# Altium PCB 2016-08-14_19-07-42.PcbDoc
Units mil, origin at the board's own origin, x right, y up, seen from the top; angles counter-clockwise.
Board outline 2760 x 2755 mil, 4 copper layers (Top Layer, MidLayer1, MidLayer2, Bottom Layer); 18 components, 10 nets, 39 pads, 47 vias.
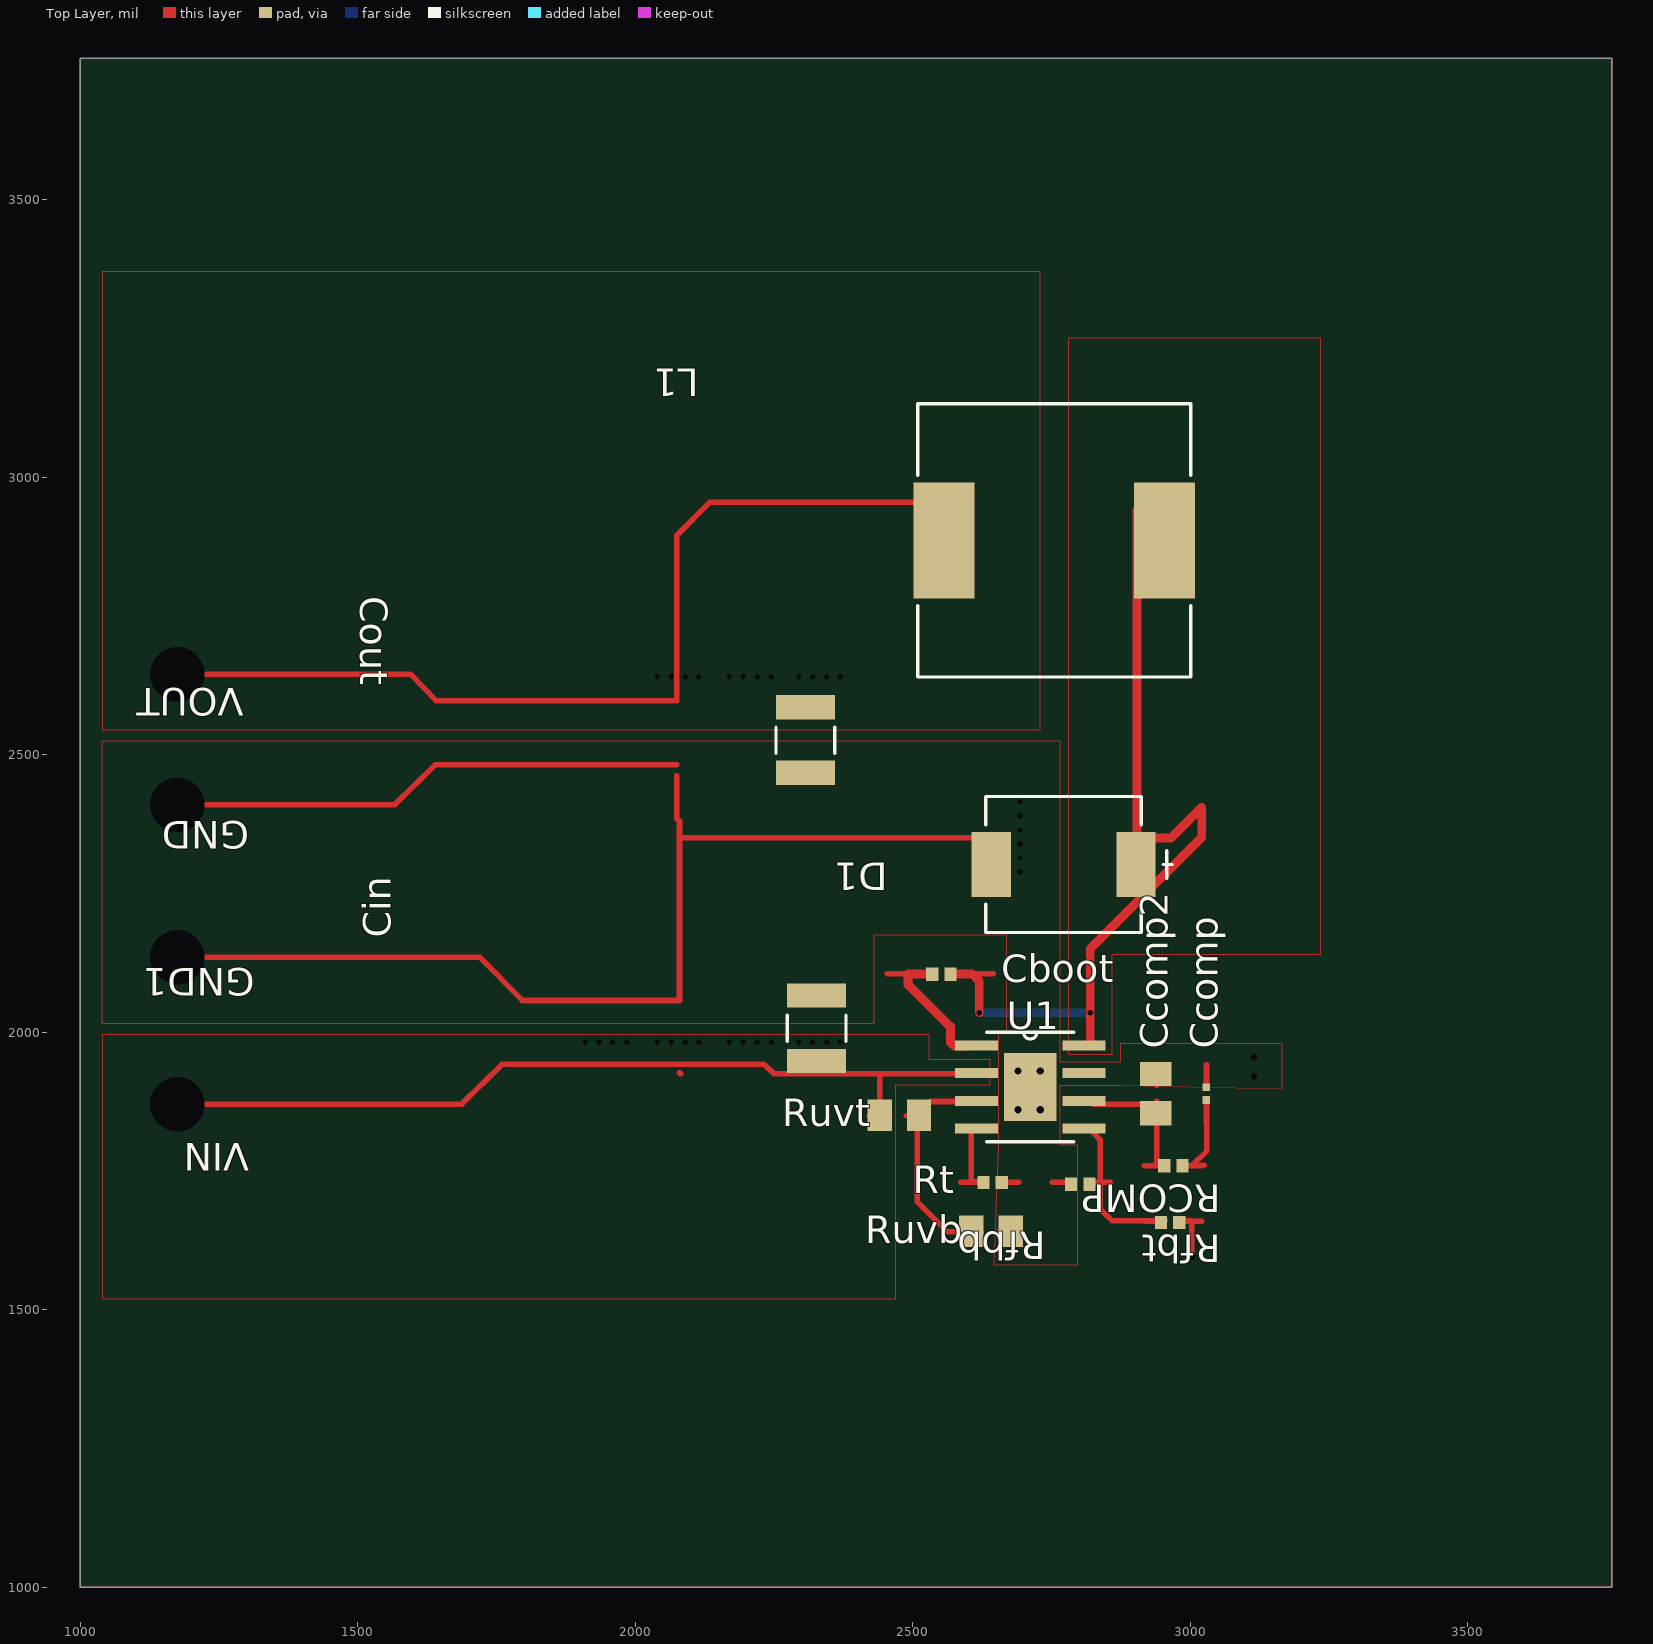
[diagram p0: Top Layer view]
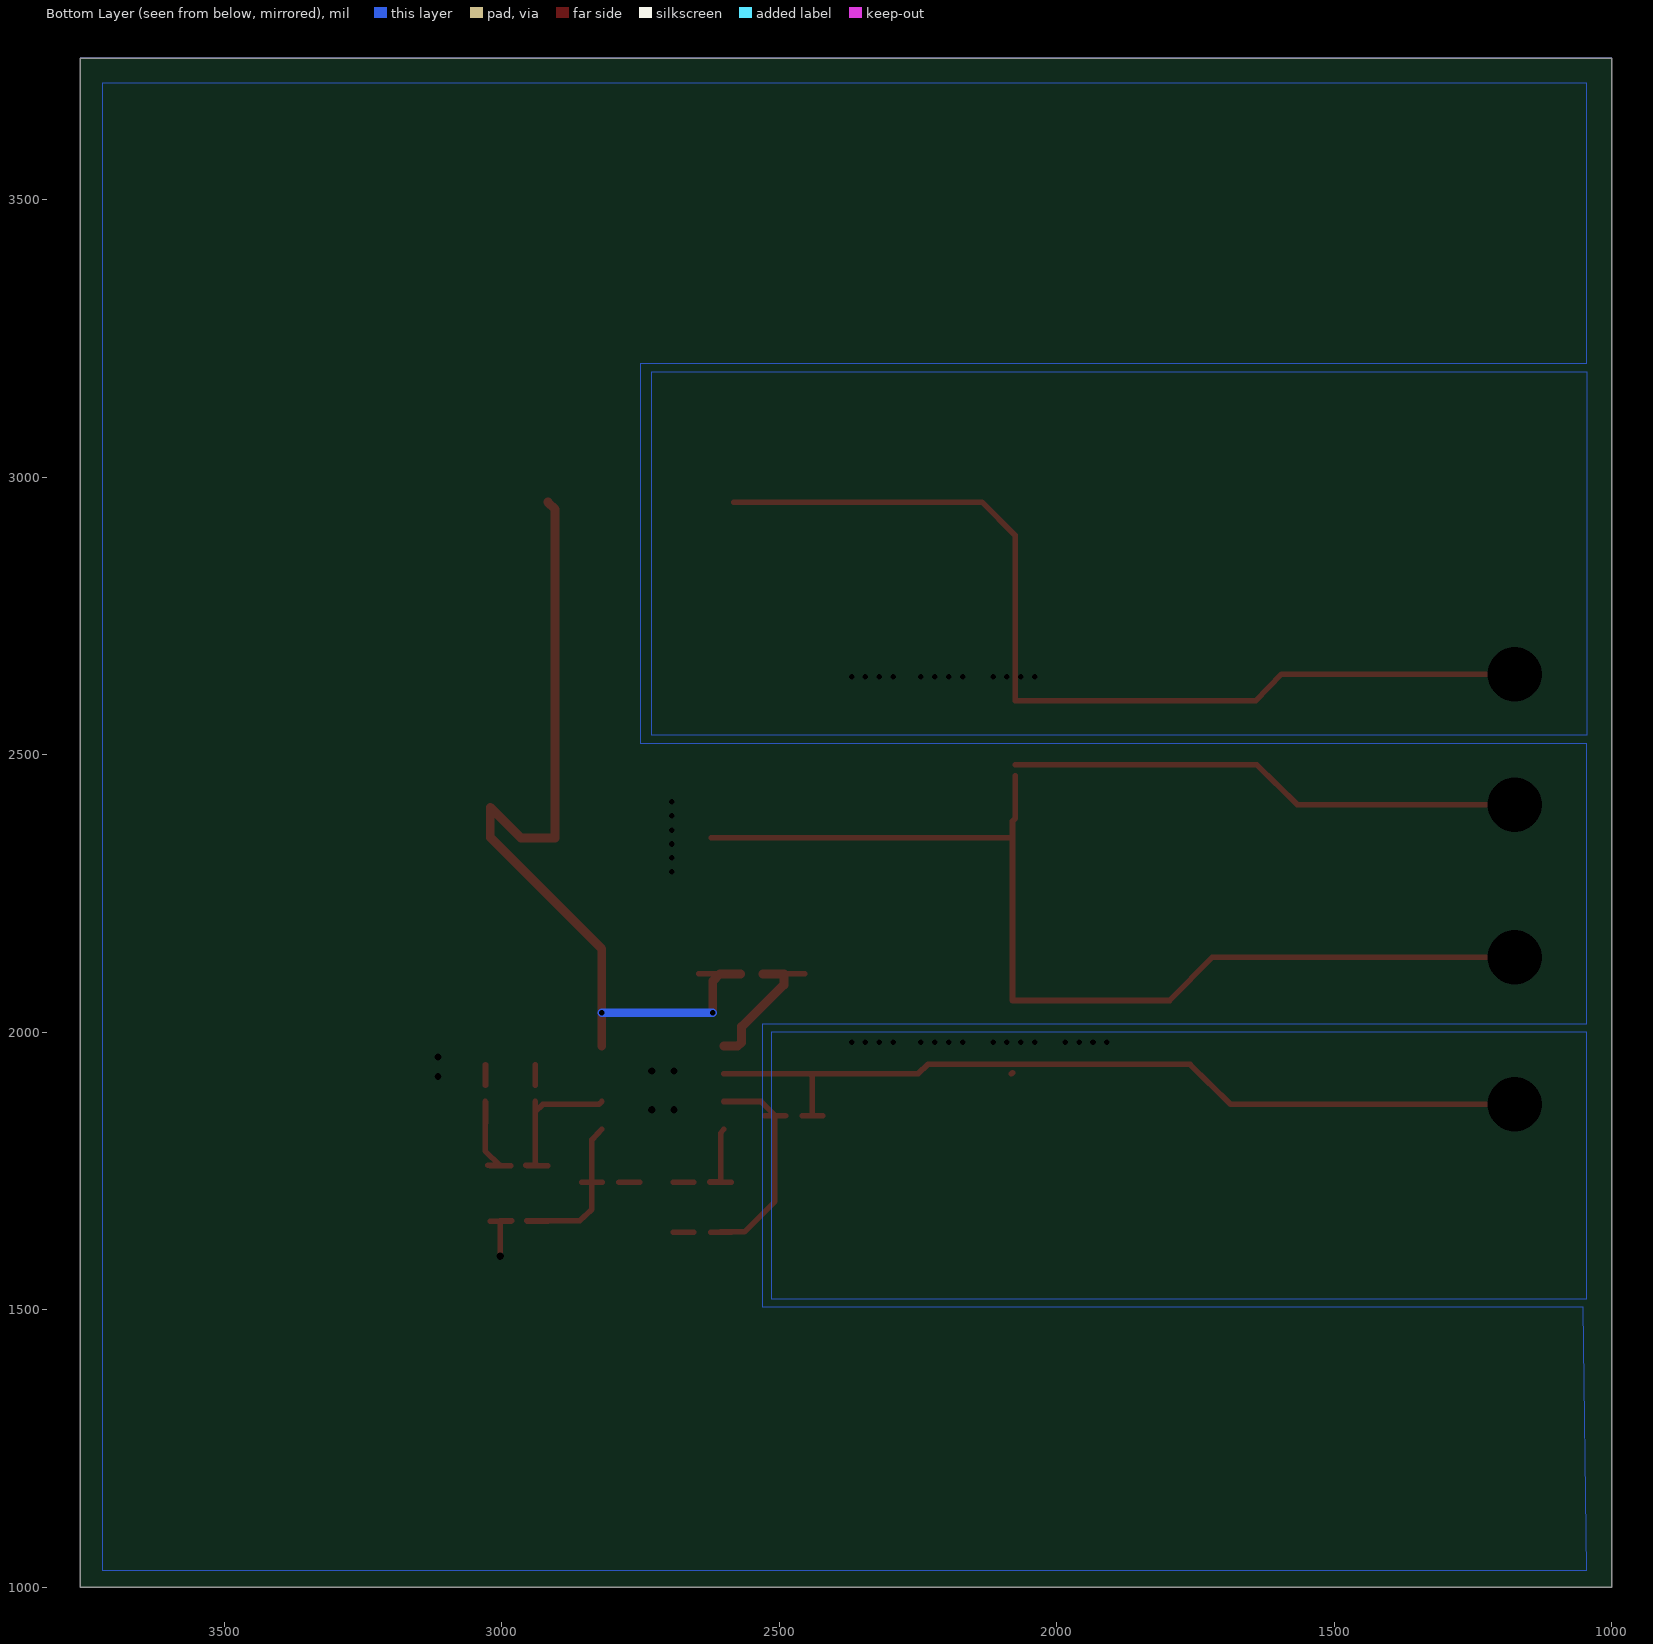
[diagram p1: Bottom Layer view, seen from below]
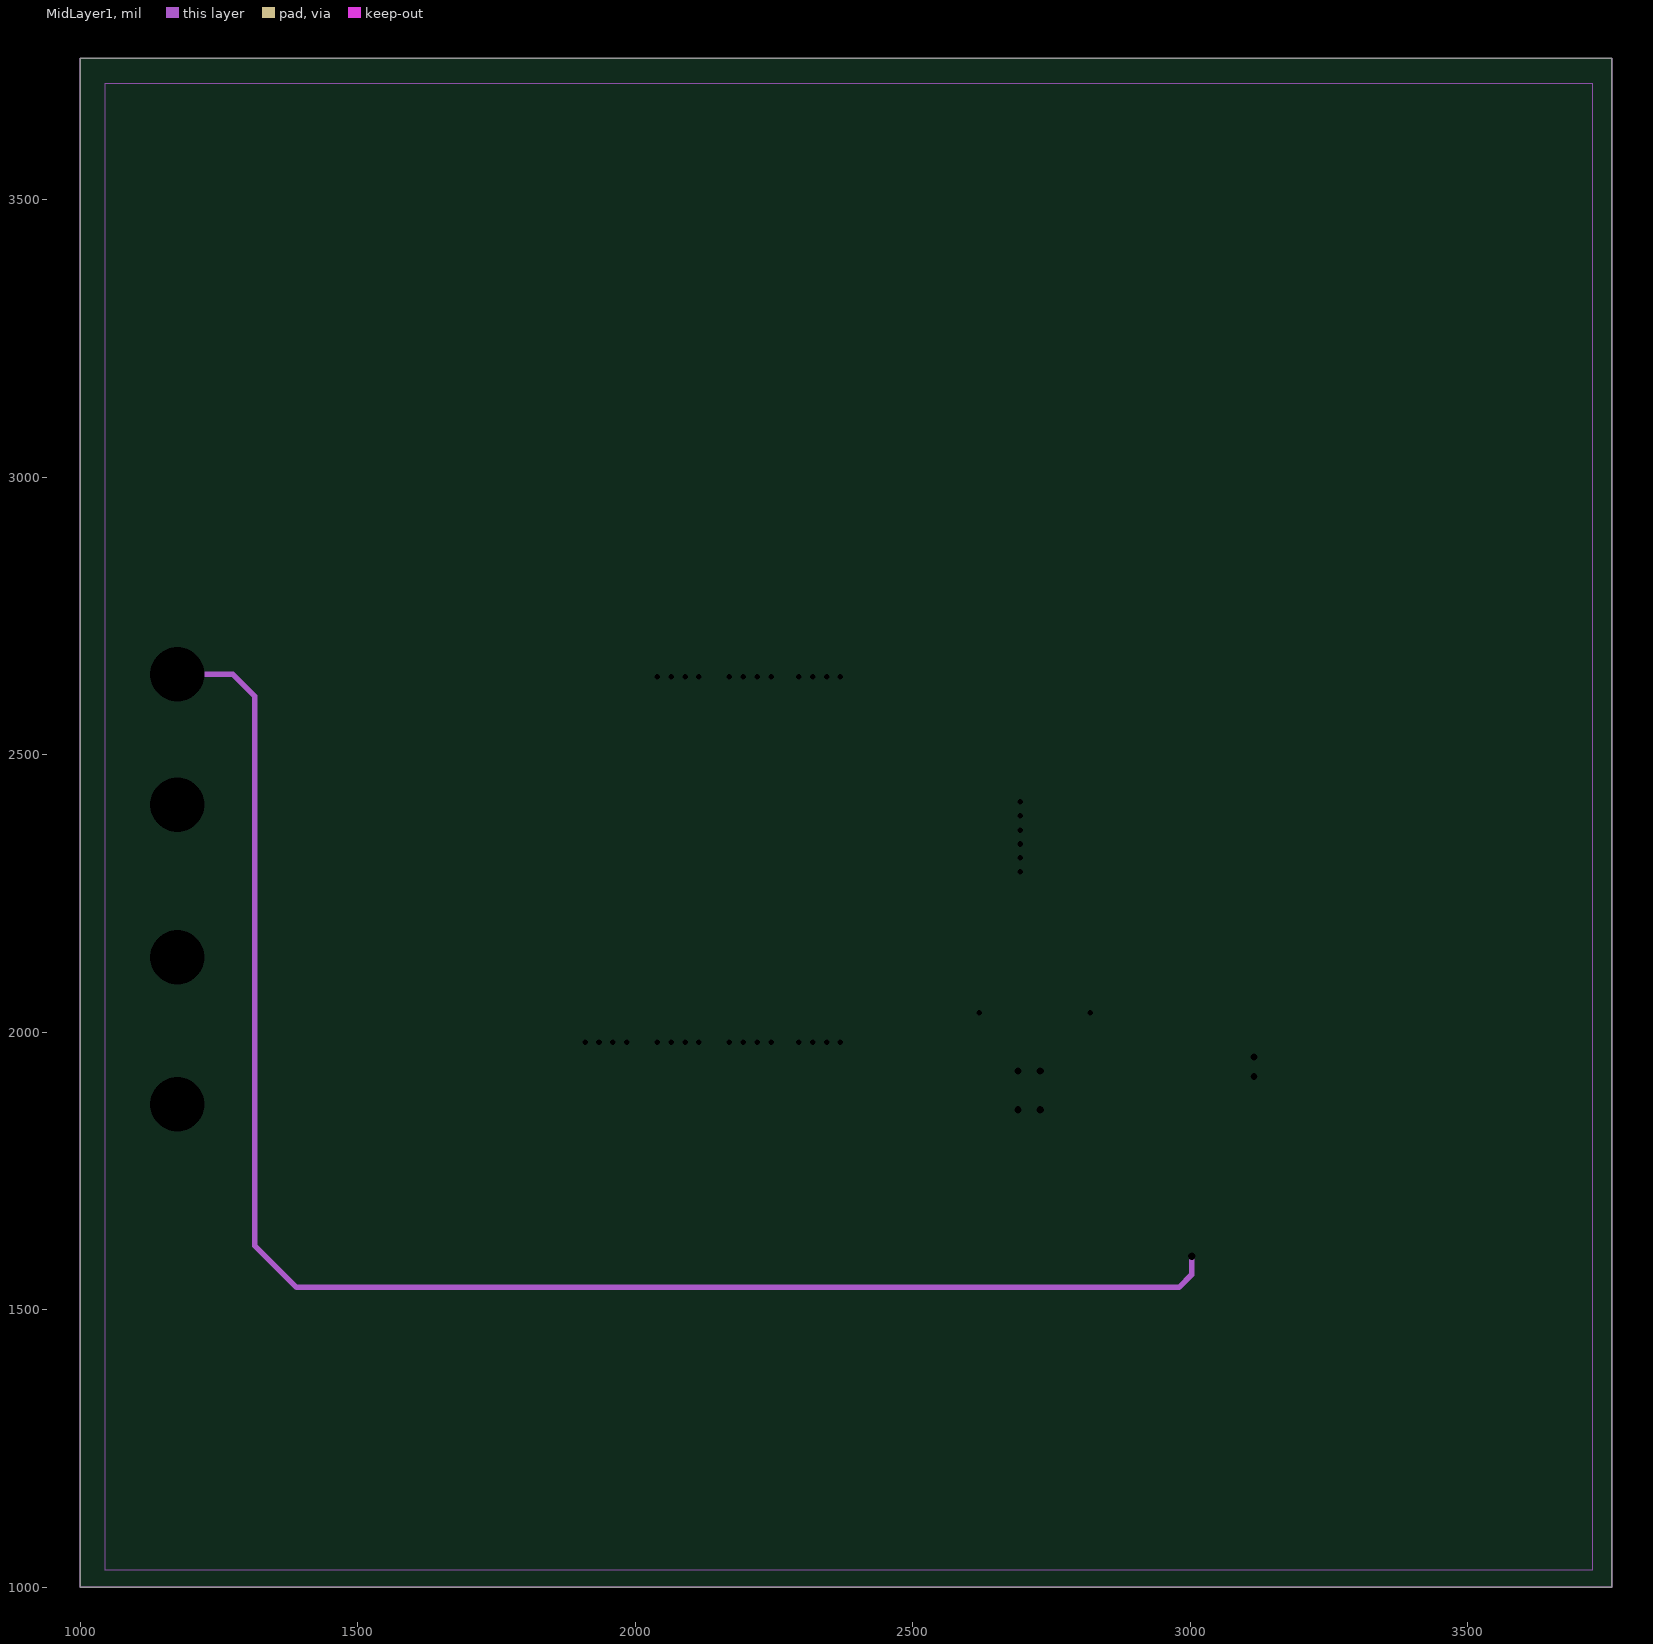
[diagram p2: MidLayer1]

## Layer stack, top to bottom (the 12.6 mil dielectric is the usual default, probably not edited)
Top Layer: signal copper 1.4
Dielectric: core 12.6, FR-4, Dk 4.8
MidLayer1: signal copper 1.4
Dielectric: prepreg 12.6, FR-4, Dk 4.8
MidLayer2: signal copper 1.4
Dielectric: core 12.6, FR-4, Dk 4.8
Bottom Layer: signal copper 1.4

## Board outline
1000,1000 3760,1000 3760,3755 1000,3755

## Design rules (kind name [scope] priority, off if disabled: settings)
PlaneConnect [All] p0: scope1count=1 scope1_0_kind=Board scope1_0_value=Board scope2count=1 scope2_0_kind=Board scope2_0_value=Board commentlength=0 planeconnectstyle=Direct reliefexpansion=20 reliefentries=4 reliefconductorwidth=10 reliefairgap=10
PlaneConnect [All] p1: planeconnectstyle=Direct reliefexpansion=20 reliefentries=4 reliefconductorwidth=10 reliefairgap=10
PolygonConnect [All] p0: scope1count=1 scope1_0_kind=Board scope1_0_value=Board scope2count=1 scope2_0_kind=Board scope2_0_value=Board commentlength=0 connectstyle=Direct reliefconductorwidth=10 reliefentries=4 polygonreliefangle="90 Angle"
PolygonConnect [All] p1: connectstyle=Direct reliefconductorwidth=10 reliefentries=4 polygonreliefangle="90 Angle"

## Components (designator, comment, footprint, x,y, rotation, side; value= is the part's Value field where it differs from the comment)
Cboot "" 0402 2552,2104 r0 top
Ccomp "" 0201 3029,1889 r90 top
Ccomp2 "" 0805 2938,1889 r90 top
Cin "" 1210 2327,2007 r90 top
Cout "" 1210_280 2307,2526 r270 top
D1 "" SMC 2772,2302 r180 top
GND "" TP-1502 1174,2409 r180 top
GND1 "" TP-1502 1174,2133 r180 top
L1 "" SRR1210 2755,2886 r180 top
RCOMP "" 0402 2970,1759 r180 top
Rfbb "" 0402 2802,1726 r180 top
Rfbt "" 0402 2964,1657 r180 top
Rt "" 0402 2644,1729 r0 top
Ruvb "" 0805 2641,1641 r0 top
Ruvt "" 0805 2476,1850 r0 top
U1 "" R-PDSO-G8 2712,1901 r0 top
VIN "" TP-1502 1174,1870 r180 top
VOUT "" TP-1502 1174,2644 r180 top

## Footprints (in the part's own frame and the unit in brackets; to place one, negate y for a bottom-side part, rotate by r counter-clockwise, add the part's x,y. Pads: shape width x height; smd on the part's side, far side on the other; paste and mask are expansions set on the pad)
0201 [mil]
  rect 14x13 smd: 1(-11.5,0) 2(11.5,0)
0402 [mil]
  rect 22x24 smd: 1(-16.5,0) 2(16.5,0)
0805 [mil]
  rect 44x57 smd: 1(-35.5,0) 2(35.5,0)
1210 [mil]
  rect 44x106 smd: 1(-59,0) 2(59,0)
  silkscreen extent -24,-53 24,53
1210_280 [mil]
  rect 44x106 smd: 1(-59,0) 2(59,0)
  silkscreen extent -24,-53 24,53
R-PDSO-G8 [mil]
  rect 78x18.14 smd: 1(-97,75) 2(-97,25) 3(-97,-25) 4(-97,-75) 5(97,-75) 6(97,-25) 7(97,25) 8(97,75)
  rect 94x122 smd: 9(0,0)
  silkscreen extent -78,-98 78,98
SMC [mil]
  rect 71x117 smd: 1(-130.5,0) 2(130.5,0)
  silkscreen extent -196,-123 140,123
SRR1210 [mil]
  rect 110x209 smd: 1(-198.5,0) 2(198.5,0)
  silkscreen extent -246,-246 246,246
TP-1502 [mil]
  round 65 / inner round 0 / far side round 65 hole 32: 1(0,0)

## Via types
v1: diameter 0, hole 10, Top Layer to Bottom Layer, 36 vias
v2: diameter 0, hole 13, Top Layer to Bottom Layer, 7 vias
v3: diameter 0, hole 98, Top Layer to Bottom Layer, 4 vias

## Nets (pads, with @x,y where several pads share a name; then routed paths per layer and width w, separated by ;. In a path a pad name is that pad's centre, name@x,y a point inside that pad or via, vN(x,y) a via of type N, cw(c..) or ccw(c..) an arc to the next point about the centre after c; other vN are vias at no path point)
0: Ccomp2.2 Ccomp.2 Cin.2 Cout.2 D1.2 GND1.1 GND.1 Rfbb.2 Rt.2 Ruvb.2 U1.7 U1.9 | length 3002.2
  Top Layer w10: v3(1175,2135) 1720,2135 1797,2057 2080,2057 2080,2350 ; v3(1175,2410) 1567,2410 1640,2482 2075,2482 ; 2075,2462 2075,2385 2080,2380 2080,2350 ; D1.2@2623,2350 2080,2350 ; 2654,1639.5 Ruvb.2@2691,1639.5 ; Rt.2@2654,1729.5 2691,1729.5 ; 2752,1729.5 Rfbb.2@2789,1729.5 ; Ccomp2.2@2939.5,1904 Ccomp2.2@2939.5,1941 ; Ccomp.2@3029.5,1904 3029.5,1941
  other v1: 2694,2289 2694,2314 2694,2339 2694,2364 2694,2390 2694,2415
  other v2: 2690,1860 2730,1860 3115,1920 2690,1930 2730,1930 3115,1955
1: Ccomp2.1 RCOMP.2 U1.6 | length 339.9
  Top Layer w10: U1.6@2820,1875 2825,1870 2926,1870 Ccomp2.1@2940,1856 ; 2917,1759.5 RCOMP.2@2954,1759.5 ; Ccomp2.1@2939.5,1837 Ccomp2.1@2939.5,1874 ; Ccomp2.1@2940,1875 Ccomp2.1@2940,1856 ; RCOMP.2@2957,1760 2936,1760 2940,1763 Ccomp2.1@2940,1856
2: Rt.1 U1.4 | length 153.2
  Top Layer w10: 2587,1729.5 Rt.1@2624,1729.5 ; U1.4@2600,1825 2606,1818 2606,1730 Rt.1@2625,1730
3: Cboot.1 U1.1 | length 304
  Top Layer w10: 2454,2105 Cboot.1@2530,2105
  Top Layer w16: Cboot.1@2530,2105 2492,2105 2492,2085 2568,2010 2568,1981 2575,1975 U1.1@2600,1975
4: Rfbb.1 Rfbt.2 U1.5 | length 350.6
  Top Layer w10: Rfbb.1@2819,1729.5 2856,1729.5 ; U1.5@2820,1825 2838,1806 2838,1730 2838,1681 2860,1660 2936,1660 Rfbt.2@2955,1660 ; 2917,1659.5 Rfbt.2@2954,1659.5
5: Cboot.2 D1.1 L1.1 U1.8 | length 1651.8
  Top Layer w10: Cboot.2@2569,2105 2645,2105
  Top Layer w16: Cboot.2@2570,2105 2607,2105 2620,2092 v1(2620,2035) ; U1.8@2820,1975 2820,2150 3021,2351 3021,2405 2966,2350 2904,2350 2904,2942 L1.1@2917,2955
  Bottom Layer w16: v1(2620,2035) v1(2820,2035)
6: Cin.1 Ruvt.1 U1.2 VIN.1 | length 1577.8
  Top Layer w10: v3(1175,1870) 1687,1870 1760,1942 2080,1942 2232,1942 2250,1925 2445,1925 ; 2080,1927 2082,1925 ; Ruvt.1@2422,1849.5 Ruvt.1@2459,1849.5 ; Ruvt.1@2441,1850 2441,1921 2445,1925 ; U1.2@2600,1925 2445,1925
  other v1: 1910,1982 1935,1982 1960,1982 1985,1982 2040,1982 2065,1982 2090,1982 2115,1982 2170,1982 2195,1982 2220,1982 2245,1982 2295,1982 2320,1982 2345,1982 2370,1982
7: Cout.1 L1.2 Rfbt.1 VOUT.1 | length 4780.2
  Top Layer w10: v3(1175,2645) 1595,2645 1642,2597 2075,2597 2075,2895 2135,2955 L1.2@2582,2955 ; Rfbt.1@2982,1660 3003,1660 v2(3003,1596) ; Rfbt.1@2984,1659.5 3021,1659.5
  MidLayer1 w10: v3(1175,2645) 1275,2645 1315,2605 1315,1615 1390,1540 2980,1540 3003,1563 v2(3003,1596)
  other v1: 2040,2640 2065,2640 2090,2640 2115,2640 2170,2640 2195,2640 2220,2640 2245,2640 2295,2640 2320,2640 2345,2640 2370,2640
8: Ccomp.1 RCOMP.1 | length 222.5
  Top Layer w10: RCOMP.1@2984,1759.5 3021,1759.5 ; 3025,1760 3003,1760 3030,1786 3030,1856 Ccomp.1@3030,1875 ; 3029.5,1837 Ccomp.1@3029.5,1874
17: Ruvb.1 Ruvt.2 U1.3 | length 452.1
  Top Layer w10: 2489,1849.5 Ruvt.2@2526,1849.5 ; Ruvb.1@2587,1639.5 Ruvb.1@2624,1639.5 ; U1.3@2600,1875 2533,1875 2508,1850 2508,1695 2563,1640 Ruvb.1@2606,1640

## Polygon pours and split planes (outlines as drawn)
6 on Top Layer " " (solid, pour order 0): 1040,1995 1040,1520 2470,1520 2470,1905 2495,1905 2640,1905 2640,1950 2530,1950 2530,1995
5 on Top Layer " " (solid, pour order 1): 2780,1960 2860,1960 2860,2140 3235,2140 3235,3250 2780,3250
7 on Top Layer " " (solid, pour order 2): 1040,2545 2730,2545 2730,3370 1040,3370
0 on Top Layer " " (solid, pour order 5): 1040,2015 1040,2525 2765,2525 2765,1947 2875,1947 2875,1980 3165,1980 3165,1897 2875,1903 2765,1903 2765,1797 2797,1797 2797,1580 2647,1580 2655,1797 2655,2000 2670,2000 2670,2175 2430,2175 2430,2015
6 on Bottom Layer " " (solid, pour order 3): 1045,2000 2515,2000 2515,1520 1045,1520
7 on Bottom Layer " " (solid, pour order 4): 1045,2535 2730,2535 2730,2625 2730,3190 2710,3190 1045,3190
0 on Bottom Layer " " (solid, pour order 8): 1045,1030 1052,1504 2530,1504 2530,1550 2530,2015 1045,2015 1045,2520 2460,2520 2750,2520 2750,3205 2415,3205 1045,3205 1045,3710 3720,3710 3720,1030
0 on MidLayer1 " " (solid, pour order 6): 1045,3710 3725,3710 3725,1030 1045,1030
0 on MidLayer2 " " (solid, pour order 7): 1045,3710 1045,1030 3725,1030 3725,3710

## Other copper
Multi-Layer:
  the board outline again, w1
